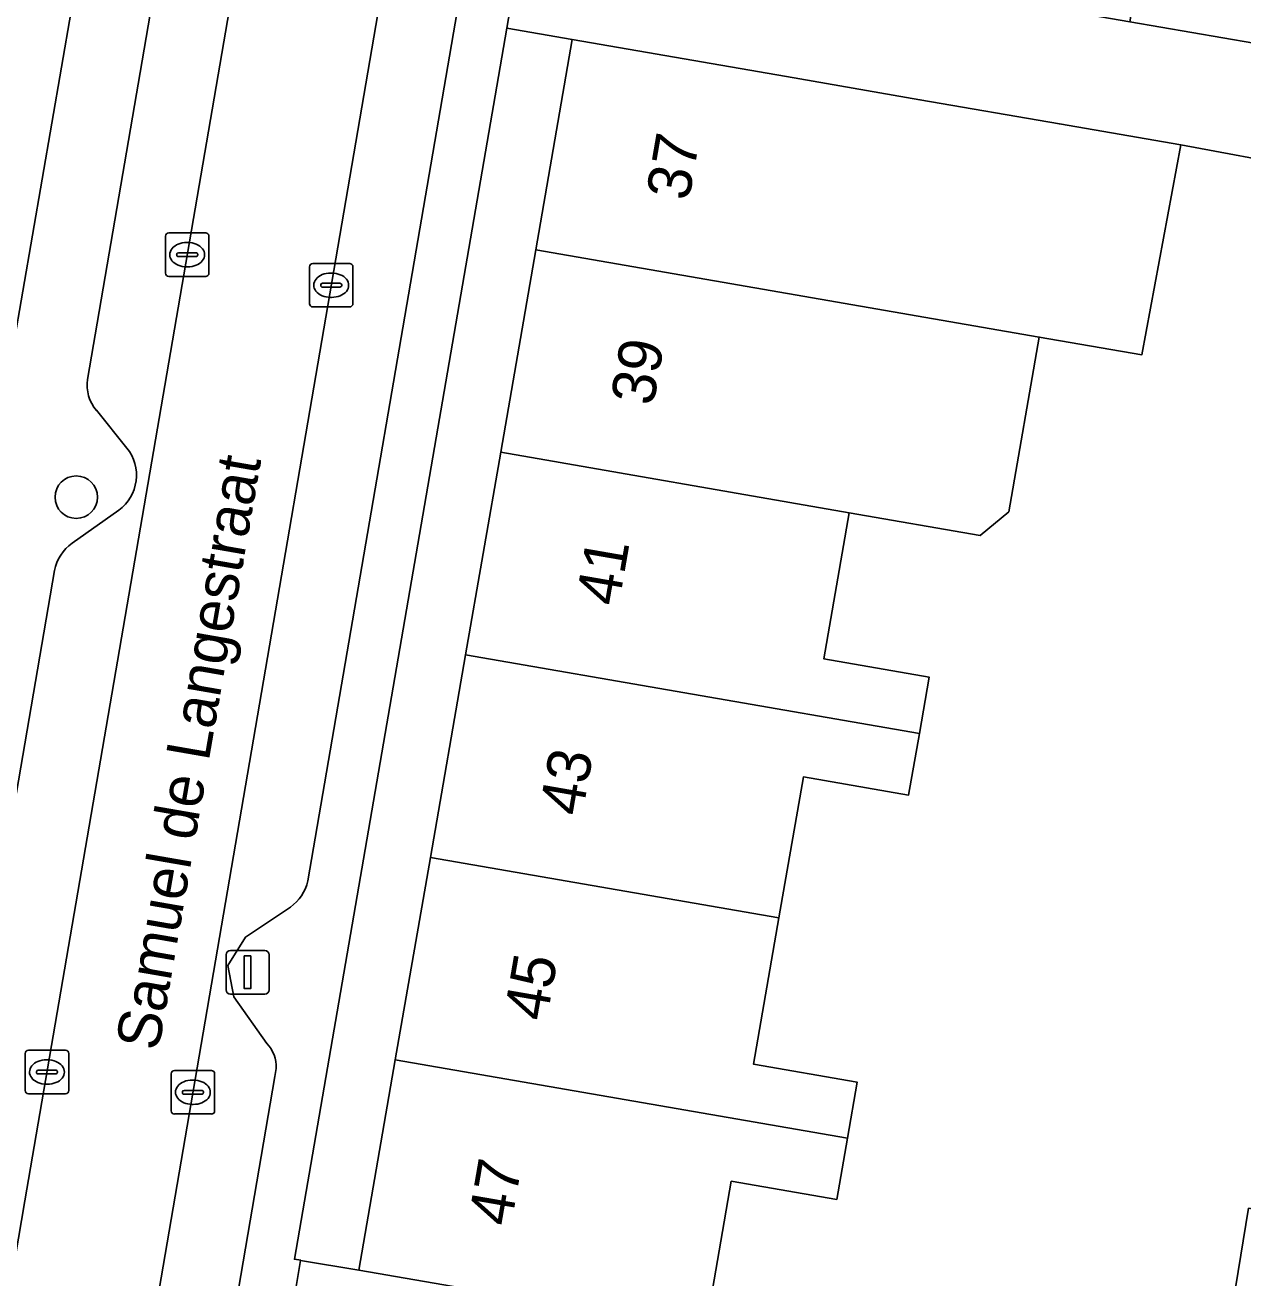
# Model space of a CAD drawing. Extents: x 159817 to 160765, y 380688 to 381638.
# Drawn here: x 160112.52 to 160140.53, y 380902.82 to 380931.65 of the extents above; entities that cross this region are included whole.
import ezdxf

# ---------------------------------------------------------------- set-up
doc = ezdxf.new("R2010")
doc.units = 0
for name, color, linetype in [('IMGEO_Boom', 7, 'Continuous'), ('IMGEO_Erf', 7, 'Continuous'), ('IMGEO_Kolk', 7, 'Continuous'), ('IMGEO_Lichtmast', 7, 'Continuous'), ('IMGEO_Openbare_ruimte_label', 7, 'Continuous'), ('IMGEO_Pand', 7, 'Continuous'), ('IMGEO_Pand_nummerreeks', 7, 'Continuous'), ('IMGEO_Parkeervlak_open', 7, 'Continuous'), ('IMGEO_Rijbaan_lokaal_open', 7, 'Continuous'), ('IMGEO_Voetpad_open', 7, 'Continuous')]:
    doc.layers.add(name, color=color, linetype=linetype)

msp = doc.modelspace()

# ---------------------------------------------------------------- linework, layer by layer
at = {"layer": 'IMGEO_Boom'}
msp.add_circle((160113.694, 380920.784), 0.489, dxfattribs=at)
at = {"layer": 'IMGEO_Erf'}
for points in [[(160144.522, 380942.987), (160146.098, 380942.683), (160146.878, 380947.827), (160150.745, 380947.241), (160150.748, 380947.258), (160138.361, 380949.392), (160137.362, 380943.589), (160140.211, 380943.098), (160139.242, 380937.467), (160140.404, 380937.267), (160139.755, 380933.501), (160138.283, 380933.755), (160137.932, 380931.72), (160147.918, 380930.001), (160148.319, 380932.446), (160145.698, 380932.876), (160146.253, 380936.26), (160146.329, 380936.722), (160143.569, 380937.174)], [(160113.802, 380933.264), (160112.275, 380933.528), (160111.436, 380928.688), (160110.626, 380924.02), (160109.817, 380919.352), (160109.008, 380914.683), (160108.198, 380910.015), (160107.359, 380905.174), (160108.896, 380904.908)], [(160122.65, 380917.158), (160123.458, 380921.818), (160124.266, 380926.478), (160125.104, 380931.314), (160123.6, 380931.573), (160118.714, 380903.25), (160118.857, 380903.225), (160118.856, 380903.222), (160120.195, 380902.998), (160121.034, 380907.836), (160121.842, 380912.497)]]:
    msp.add_lwpolyline(points, close=True, dxfattribs=at)
for points in [[(160144.699, 380927.844), (160139.108, 380928.887), (160138.208, 380924.062), (160135.848, 380924.468), (160135.15, 380920.45), (160134.491, 380919.904), (160131.473, 380920.427), (160130.89, 380917.066), (160133.314, 380916.646), (160133.089, 380915.346), (160132.843, 380913.928), (160130.421, 380914.348), (160129.859, 380911.105), (160129.275, 380907.738), (160131.657, 380907.325), (160131.433, 380906.032), (160131.189, 380904.626), (160128.762, 380905.046), (160128.168, 380901.616)], [(160140.065, 380900.757), (160140.663, 380904.422)]]:
    msp.add_lwpolyline(points, dxfattribs=at)
at = {"layer": 'IMGEO_Kolk'}
for p, q in [((160115.745, 380925.937), (160115.745, 380926.789)), ((160115.82, 380926.863), (160116.672, 380926.863)), ((160116.233, 380926.643), (160116.258, 380926.643)), ((160116.746, 380926.789), (160116.746, 380925.937)), ((160116.004, 380926.357), (160116.004, 380926.369)), ((160116.047, 380926.406), (160116.445, 380926.406)), ((160116.488, 380926.369), (160116.488, 380926.357)), ((160116.442, 380926.32), (160116.044, 380926.32)), ((160116.256, 380926.083), (160116.231, 380926.083)), ((160119.058, 380925.235), (160119.058, 380926.087)), ((160119.133, 380926.161), (160119.985, 380926.161)), ((160120.059, 380926.087), (160120.059, 380925.235)), ((160116.672, 380925.863), (160115.82, 380925.863)), ((160119.546, 380925.941), (160119.571, 380925.941)), ((160119.317, 380925.655), (160119.317, 380925.667)), ((160119.755, 380925.618), (160119.357, 380925.618)), ((160119.36, 380925.704), (160119.758, 380925.704)), ((160119.801, 380925.667), (160119.801, 380925.655)), ((160119.569, 380925.381), (160119.544, 380925.381)), ((160119.985, 380925.161), (160119.133, 380925.161)), ((160112.519, 380907.132), (160112.519, 380907.984)), ((160112.594, 380908.058), (160113.446, 380908.058)), ((160113.52, 380907.984), (160113.52, 380907.132)), ((160112.821, 380907.601), (160113.219, 380907.601)), ((160113.007, 380907.838), (160113.032, 380907.838)), ((160115.951, 380907.592), (160116.803, 380907.592)), ((160112.778, 380907.552), (160112.778, 380907.564)), ((160113.216, 380907.515), (160112.818, 380907.515)), ((160113.262, 380907.564), (160113.262, 380907.552)), ((160115.876, 380906.666), (160115.876, 380907.518)), ((160116.364, 380907.372), (160116.389, 380907.372)), ((160116.877, 380907.518), (160116.877, 380906.666)), ((160113.446, 380907.058), (160112.594, 380907.058)), ((160113.03, 380907.278), (160113.005, 380907.278)), ((160116.135, 380907.086), (160116.135, 380907.098)), ((160116.573, 380907.049), (160116.175, 380907.049)), ((160116.178, 380907.135), (160116.576, 380907.135)), ((160116.619, 380907.098), (160116.619, 380907.086)), ((160116.387, 380906.812), (160116.362, 380906.812)), ((160116.803, 380906.592), (160115.951, 380906.592))]:
    msp.add_line(p, q, dxfattribs=at)
for points in [[(160115.745, 380925.937), (160115.745, 380926.789)], [(160115.82, 380926.863), (160116.672, 380926.863)], [(160116.746, 380926.789), (160116.746, 380925.937)], [(160119.058, 380925.235), (160119.058, 380926.087)], [(160119.133, 380926.161), (160119.985, 380926.161)], [(160120.059, 380926.087), (160120.059, 380925.235)], [(160116.672, 380925.863), (160115.82, 380925.863)], [(160119.985, 380925.161), (160119.133, 380925.161)], [(160112.519, 380907.132), (160112.519, 380907.984)], [(160112.594, 380908.058), (160113.446, 380908.058)], [(160113.52, 380907.984), (160113.52, 380907.132)], [(160115.951, 380907.592), (160116.803, 380907.592)], [(160115.876, 380906.666), (160115.876, 380907.518)], [(160116.877, 380907.518), (160116.877, 380906.666)], [(160113.446, 380907.058), (160112.594, 380907.058)], [(160116.803, 380906.592), (160115.951, 380906.592)]]:
    msp.add_lwpolyline(points, dxfattribs=at)
for centre, radius, start, end in [((160115.822, 380926.787), 0.0765, 91.552, 178.448), ((160115.822, 380926.787), 0.0765, 91.552, 178.448), ((160116.67, 380926.787), 0.0765, 1.552, 88.448), ((160116.67, 380926.787), 0.0765, 1.552, 88.448), ((160116.044, 380926.366), 0.0403, 85.8775, 175.7526), ((160116.041, 380926.356), 0.0366, 178.938, 274.7102), ((160116.445, 380926.363), 0.043, 264.8664, 352.4533), ((160116.449, 380926.368), 0.0386, 1.7309, 96.639), ((160119.135, 380926.085), 0.0765, 91.552, 178.448), ((160119.135, 380926.085), 0.0765, 91.552, 178.448), ((160119.983, 380926.085), 0.0765, 1.552, 88.448), ((160119.983, 380926.085), 0.0765, 1.552, 88.448), ((160115.822, 380925.939), 0.0765, 181.552, 268.448), ((160115.822, 380925.939), 0.0765, 181.552, 268.448), ((160116.67, 380925.939), 0.0765, 271.552, 358.448), ((160116.67, 380925.939), 0.0765, 271.552, 358.448), ((160119.357, 380925.664), 0.0403, 85.8775, 175.7526), ((160119.354, 380925.654), 0.0366, 178.938, 274.7102), ((160119.758, 380925.661), 0.043, 264.8664, 352.4533), ((160119.762, 380925.666), 0.0386, 1.7309, 96.639), ((160119.135, 380925.237), 0.0765, 181.552, 268.448), ((160119.135, 380925.237), 0.0765, 181.552, 268.448), ((160119.983, 380925.237), 0.0765, 271.552, 358.448), ((160119.983, 380925.237), 0.0765, 271.552, 358.448), ((160112.596, 380907.982), 0.0765, 91.552, 178.448), ((160112.596, 380907.982), 0.0765, 91.552, 178.448), ((160113.444, 380907.982), 0.0765, 1.552, 88.448), ((160113.444, 380907.982), 0.0765, 1.552, 88.448), ((160112.818, 380907.561), 0.0403, 85.8775, 175.7526), ((160113.223, 380907.563), 0.0386, 1.7309, 96.639), ((160115.953, 380907.516), 0.0765, 91.552, 178.448), ((160115.953, 380907.516), 0.0765, 91.552, 178.448), ((160116.801, 380907.516), 0.0765, 1.552, 88.448), ((160116.801, 380907.516), 0.0765, 1.552, 88.448), ((160112.815, 380907.551), 0.0366, 178.938, 274.7102), ((160113.219, 380907.558), 0.043, 264.8664, 352.4533), ((160112.596, 380907.134), 0.0765, 181.552, 268.448), ((160112.596, 380907.134), 0.0765, 181.552, 268.448), ((160113.444, 380907.134), 0.0765, 271.552, 358.448), ((160113.444, 380907.134), 0.0765, 271.552, 358.448), ((160116.175, 380907.095), 0.0403, 85.8775, 175.7526), ((160116.172, 380907.085), 0.0366, 178.938, 274.7102), ((160116.576, 380907.092), 0.043, 264.8664, 352.4533), ((160116.58, 380907.097), 0.0386, 1.7309, 96.639), ((160115.953, 380906.668), 0.0765, 181.552, 268.448), ((160115.953, 380906.668), 0.0765, 181.552, 268.448), ((160116.801, 380906.668), 0.0765, 271.552, 358.448), ((160116.801, 380906.668), 0.0765, 271.552, 358.448)]:
    msp.add_arc(centre, radius, start, end, dxfattribs=at)
for centre, major_axis, ratio, start_param, end_param in [((160116.232, 380926.363), (-0.387, 0.002), 0.722429, 4.712389, 7.853982), ((160116.257, 380926.363), (-0.39, 0.002), 0.717154, 1.570796, 4.712389), ((160119.545, 380925.661), (-0.387, 0.002), 0.722429, 4.712389, 7.853982), ((160119.57, 380925.661), (-0.39, 0.002), 0.717154, 1.570796, 4.712389), ((160113.006, 380907.558), (-0.387, 0.002), 0.722429, 4.712389, 7.853982), ((160113.031, 380907.558), (-0.39, 0.002), 0.717154, 1.570796, 4.712389), ((160116.363, 380907.092), (-0.387, 0.002), 0.722429, 4.712389, 7.853982), ((160116.388, 380907.092), (-0.39, 0.002), 0.717154, 1.570796, 4.712389)]:
    msp.add_ellipse(centre, major_axis=major_axis, ratio=ratio, start_param=start_param, end_param=end_param, dxfattribs=at)
at = {"layer": 'IMGEO_Lichtmast'}
for p, q in [((160117.14, 380909.452), (160117.14, 380910.252)), ((160117.14, 380910.252), (160117.14, 380909.452)), ((160117.24, 380910.352), (160118.03, 380910.352)), ((160118.03, 380910.352), (160117.24, 380910.352)), ((160118.13, 380910.252), (160118.13, 380909.452)), ((160118.13, 380909.452), (160118.13, 380910.252)), ((160118.03, 380909.352), (160117.24, 380909.352)), ((160117.24, 380909.352), (160118.03, 380909.352))]:
    msp.add_line(p, q, dxfattribs=at)
msp.add_lwpolyline([(160117.56, 380910.227), (160117.71, 380910.227), (160117.71, 380909.477), (160117.56, 380909.477), (160117.56, 380910.227)], dxfattribs=at)
for centre, start, end in [((160117.24, 380910.252), 90, 180), ((160117.24, 380910.252), 90, 180), ((160118.03, 380910.252), 0, 90), ((160118.03, 380910.252), 360, 90), ((160117.24, 380909.452), 180, 270), ((160117.24, 380909.452), 180, 270), ((160118.03, 380909.452), 270, 0), ((160118.03, 380909.452), 270, 0)]:
    msp.add_arc(centre, 0.1, start, end, dxfattribs=at)
at = {"layer": 'IMGEO_Pand'}
for points in [[(160124.266, 380926.478), (160135.848, 380924.468), (160138.208, 380924.062), (160139.108, 380928.887), (160136.31, 380929.37), (160133.102, 380929.927), (160130.031, 380930.46), (160125.104, 380931.314)], [(160123.458, 380921.818), (160131.473, 380920.427), (160134.491, 380919.904), (160135.15, 380920.45), (160135.848, 380924.468), (160124.266, 380926.478)], [(160123.458, 380921.818), (160122.65, 380917.158), (160133.089, 380915.346), (160133.314, 380916.646), (160130.89, 380917.066), (160131.473, 380920.427)], [(160121.842, 380912.497), (160129.859, 380911.105), (160130.421, 380914.348), (160132.843, 380913.928), (160133.089, 380915.346), (160122.65, 380917.158)], [(160121.842, 380912.497), (160121.034, 380907.836), (160131.433, 380906.032), (160131.657, 380907.325), (160129.275, 380907.738), (160129.859, 380911.105)], [(160131.433, 380906.032), (160121.034, 380907.836), (160120.195, 380902.998), (160125.122, 380902.144), (160128.168, 380901.616), (160128.762, 380905.046), (160131.189, 380904.626)], [(160143.416, 380903.944), (160140.663, 380904.422), (160140.065, 380900.757), (160139.698, 380900.817), (160139.531, 380900.844), (160138.876, 380900.951), (160138.701, 380899.881), (160139.12, 380899.812), (160142.647, 380899.236), (160142.685, 380899.47)]]:
    msp.add_lwpolyline(points, close=True, dxfattribs=at)
at = {"layer": 'IMGEO_Parkeervlak_open'}
for points in [[(160112.512, 380904.594), (160120.309, 380950.025), (160120.402, 380950.566), (160120.092, 380949.943), (160118.604, 380948.851)], [(160124.888, 380947.667), (160123.835, 380949.255), (160123.746, 380949.478), (160123.718, 380949.945), (160123.634, 380949.453), (160113.751, 380891.769), (160113.376, 380884.116)], [(160116.607, 380938.972), (160113.953, 380923.494)], [(160119.02, 380911.953), (160122.538, 380932.459)], [(160114.159, 380922.782), (160114.86, 380921.914)], [(160114.674, 380920.484), (160113.6, 380919.728)], [(160113.196, 380919.095), (160111.147, 380907.181)], [(160118.077, 380908.213), (160117.321, 380909.286), (160117.18, 380910.012), (160117.589, 380910.663), (160118.621, 380911.351)], [(160115.311, 380886.625), (160115.561, 380891.657), (160118.261, 380907.458), (160118.292, 380907.642)]]:
    msp.add_lwpolyline(points, dxfattribs=at)
for centre, radius, start, end in [((160114.828, 380923.361), 0.885, 171.3845, 220.8886), ((160114.075, 380921.289), 1.004, 306.6641, 38.5142), ((160114.175, 380918.915), 0.996, 125.2969, 169.6086), ((160118.061, 380912.156), 0.98, 304.8528, 348.0751), ((160117.519, 380907.677), 0.774, 357.4132, 43.8527)]:
    msp.add_arc(centre, radius, start, end, dxfattribs=at)
at = {"layer": 'IMGEO_Rijbaan_lokaal_open'}
msp.add_lwpolyline([(160113.106, 380876.611), (160113.376, 380884.116), (160113.751, 380891.769), (160123.634, 380949.453), (160120.309, 380950.025), (160112.512, 380904.594), (160112.145, 380902.423), (160111.391, 380897.971), (160110.823, 380894.689), (160110.421, 380892.404), (160109.736, 380878.45), (160109.622, 380876.765), (160111.364, 380876.688)], close=True, dxfattribs=at)
at = {"layer": 'IMGEO_Voetpad_open'}
for points in [[(160118.604, 380948.851), (160120.092, 380949.943), (160120.402, 380950.566), (160120.62, 380951.859), (160118.846, 380952.164), (160119.614, 380956.712), (160121.388, 380956.406), (160121.639, 380957.894), (160119.865, 380958.199), (160120.614, 380962.627), (160122.386, 380962.321), (160122.575, 380963.442), (160119.128, 380964.039), (160117.654, 380955.521), (160117.224, 380953.039), (160114.243, 380935.814), (160113.802, 380933.264), (160108.896, 380904.908), (160108.656, 380903.524), (160108.066, 380900.123), (160106.808, 380892.584), (160106.335, 380881.071), (160106.316, 380880.068)], [(160116.411, 380884.119), (160116.721, 380891.622), (160117.362, 380894.233), (160118.101, 380898.814), (160118.61, 380901.747), (160118.856, 380903.222), (160118.857, 380903.225), (160118.714, 380903.25), (160123.6, 380931.573), (160124.038, 380934.113), (160127.011, 380951.348), (160127.445, 380953.861), (160128.898, 380962.283)], [(160113.953, 380923.494), (160116.607, 380938.972)], [(160147.918, 380930.001), (160137.932, 380931.72), (160135.393, 380932.157), (160132.955, 380932.577), (160128.027, 380933.425), (160124.038, 380934.113), (160123.6, 380931.573), (160125.104, 380931.314), (160130.031, 380930.46), (160133.102, 380929.927), (160136.31, 380929.37), (160139.108, 380928.887), (160144.699, 380927.844)], [(160122.538, 380932.459), (160119.02, 380911.953)], [(160114.86, 380921.914), (160114.159, 380922.782)], [(160113.6, 380919.728), (160114.674, 380920.484)], [(160111.147, 380907.181), (160113.196, 380919.095)], [(160118.621, 380911.351), (160117.589, 380910.663), (160117.18, 380910.012), (160117.321, 380909.286), (160118.077, 380908.213)], [(160118.292, 380907.642), (160118.261, 380907.458), (160115.561, 380891.657), (160115.311, 380886.625)], [(160125.122, 380902.144), (160120.195, 380902.998), (160118.856, 380903.222), (160118.61, 380901.747)]]:
    msp.add_lwpolyline(points, dxfattribs=at)
for centre, radius, start, end in [((160114.828, 380923.361), 0.885, 171.3845, 220.8886), ((160114.075, 380921.289), 1.004, 306.6641, 38.5142), ((160114.175, 380918.915), 0.996, 125.2969, 169.6086), ((160118.061, 380912.156), 0.98, 304.8528, 348.0751), ((160117.519, 380907.677), 0.774, 357.4132, 43.8527)]:
    msp.add_arc(centre, radius, start, end, dxfattribs=at)

# ---------------------------------------------------------------- texts
at = {"layer": 'IMGEO_Openbare_ruimte_label'}
msp.add_text('Samuel de Langestraat', height=1, rotation=80.1514, dxfattribs=at).set_placement((160115.582, 380908.021))
at = {"layer": 'IMGEO_Pand_nummerreeks'}
for s, p in [('37', (160127.785, 380927.58)), ('39', (160126.967, 380922.861)), ('41', (160126.169, 380918.253)), ('43', (160125.331, 380913.422)), ('45', (160124.513, 380908.703)), ('47', (160123.694, 380903.983))]:
    msp.add_text(s, height=1, rotation=80.1647, dxfattribs=at).set_placement(p)

doc.saveas('drawing.dxf')
